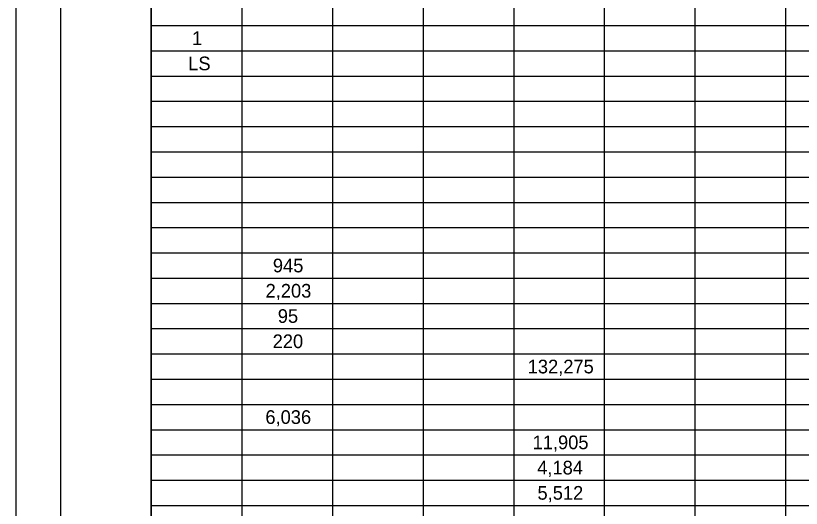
# Model space of a CAD drawing. Extents: x 0 to 34, y 0 to 22.
# Drawn here: x 0 to 8.71, y 11.11 to 16.57 of the extents above; entities that cross this region are included whole.
import ezdxf

# ---------------------------------------------------------------- set-up
doc = ezdxf.new("R2010")
doc.units = 0
for name, color, linetype in [('SH_Border', 7, 'Continuous'), ('SH_Cut_Line', 7, 'Continuous'), ('SH_Data', 7, 'Continuous')]:
    doc.layers.add(name, color=color, linetype=linetype)

msp = doc.modelspace()

# ---------------------------------------------------------------- linework, layer by layer
at = {"layer": 'SH_Border'}
for points in [[(0.5, 21.5), (1.5, 21.5), (1.5, 0.5), (0.5, 0.5)], [(1.5, 21.5), (33.5, 21.5), (33.5, 0.5), (1.5, 0.5)]]:
    msp.add_lwpolyline(points, close=True, dxfattribs=at)
at = {"layer": 'SH_Cut_Line'}
msp.add_lwpolyline([(0, 0), (34, 0), (34, 22), (0, 22)], close=True, dxfattribs=at)
at = {"layer": 'SH_Data'}
for p, q in [((1.5, 21.5), (1.5, 0.5016)), ((2.5046, 20.94), (2.5046, 0.5016)), ((3.5093, 20.94), (3.5093, 0.5016)), ((4.5139, 20.94), (4.5139, 0.5016)), ((5.5185, 20.94), (5.5185, 0.5016)), ((6.5231, 20.94), (6.5231, 0.5016)), ((7.5278, 20.94), (7.5278, 0.5016)), ((8.5324, 20.94), (8.5324, 0.5016)), ((1.5, 16.4604), (32.0011, 16.4604)), ((1.5, 16.1804), (32.0011, 16.1804)), ((1.5, 15.9004), (32.0011, 15.9004)), ((1.5, 15.6205), (32.0011, 15.6205)), ((1.5, 15.3405), (32.0011, 15.3405)), ((1.5, 15.0605), (32.0011, 15.0605)), ((1.5, 14.7805), (32.0011, 14.7805)), ((1.5, 14.5005), (32.0011, 14.5005)), ((1.5, 14.2206), (32.0011, 14.2206)), ((1.5, 13.9406), (32.0011, 13.9406)), ((1.5, 13.6606), (32.0011, 13.6606)), ((1.5, 13.3806), (32.0011, 13.3806)), ((1.5, 13.1007), (32.0011, 13.1007)), ((1.5, 12.8207), (32.0011, 12.8207)), ((1.5, 12.5407), (32.0011, 12.5407)), ((1.5, 12.2607), (32.0011, 12.2607)), ((1.5, 11.9807), (32.0011, 11.9807)), ((1.5, 11.7008), (32.0011, 11.7008)), ((1.5, 11.4208), (32.0011, 11.4208)), ((1.5, 11.1408), (32.0011, 11.1408))]:
    msp.add_line(p, q, dxfattribs=at)

# ---------------------------------------------------------------- texts
for s, height, p in [('1', 0.1515, (1.9537, 16.2446)), ('LS', 0.15152, (1.9117, 15.9647)), ('945', 0.15152, (2.85, 13.7248)), ('2,203', 0.15152, (2.769, 13.4449)), ('95', 0.15152, (2.9044, 13.1649)), ('220', 0.15152, (2.8474, 12.8849)), ('132,275', 0.15152, (5.6738, 12.6049)), ('6,036', 0.15152, (2.7667, 12.045)), ('11,905', 0.15152, (5.7282, 11.765)), ('4,184', 0.15152, (5.7794, 11.485)), ('5,512', 0.15152, (5.7823, 11.205))]:
    msp.add_text(s, height=height, dxfattribs=at).set_placement(p)

doc.saveas('drawing.dxf')
